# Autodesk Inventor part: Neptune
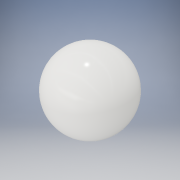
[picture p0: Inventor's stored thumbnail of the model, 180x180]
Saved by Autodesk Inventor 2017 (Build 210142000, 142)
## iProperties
Created: 2016-07
Part Number: Neptune
Material: Generic
Document SubType Name: Modeling
Designer: Stan
Density: 1 g/cm^3
Appearance: White
Author: Stan
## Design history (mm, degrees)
sketch "Sketch1"
  geometry: L1 (-3.175, -13.93)-(0, -13.93); L2 (0, 14.287)-(0, -13.93); A1 r 14.287 centre (0, 0) between (0, 14.287) and (-3.175, -13.93); 1 further point
  constraints: 4 end point, 2 point on circle, 1 centre point, 1 coincident, 1 horizontal, 1 perpendicular
  dimensions: "d0" = 28.575 diameter of A1; "d2" = 3.175 distance from line of L1.start L2; "d3" = 0 distance from line of point (0, 0) L2
revolve "Revolution1" sketch "Sketch1" stored, may be unused: angle "d4" = 90 deg
sketch "Sketch2"
  geometry: C1 r 1.587 at (0, 0); 1 further point
  constraints: 1 centre point, 1 coincident
  dimensions: "d5" = 3.175 diameter of C1
extrude "Extrusion1" cut sketch "Sketch2" distance "d6" = 6.35; taper "d7" = 0 deg
body "Solid1"
